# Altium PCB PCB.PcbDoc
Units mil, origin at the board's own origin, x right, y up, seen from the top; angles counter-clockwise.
Board outline 2000 x 1700 mil, 2 copper layers (Top Layer, Bottom Layer), stack 62 mil thick; 59 components, 36 nets, 136 pads, 43 vias.
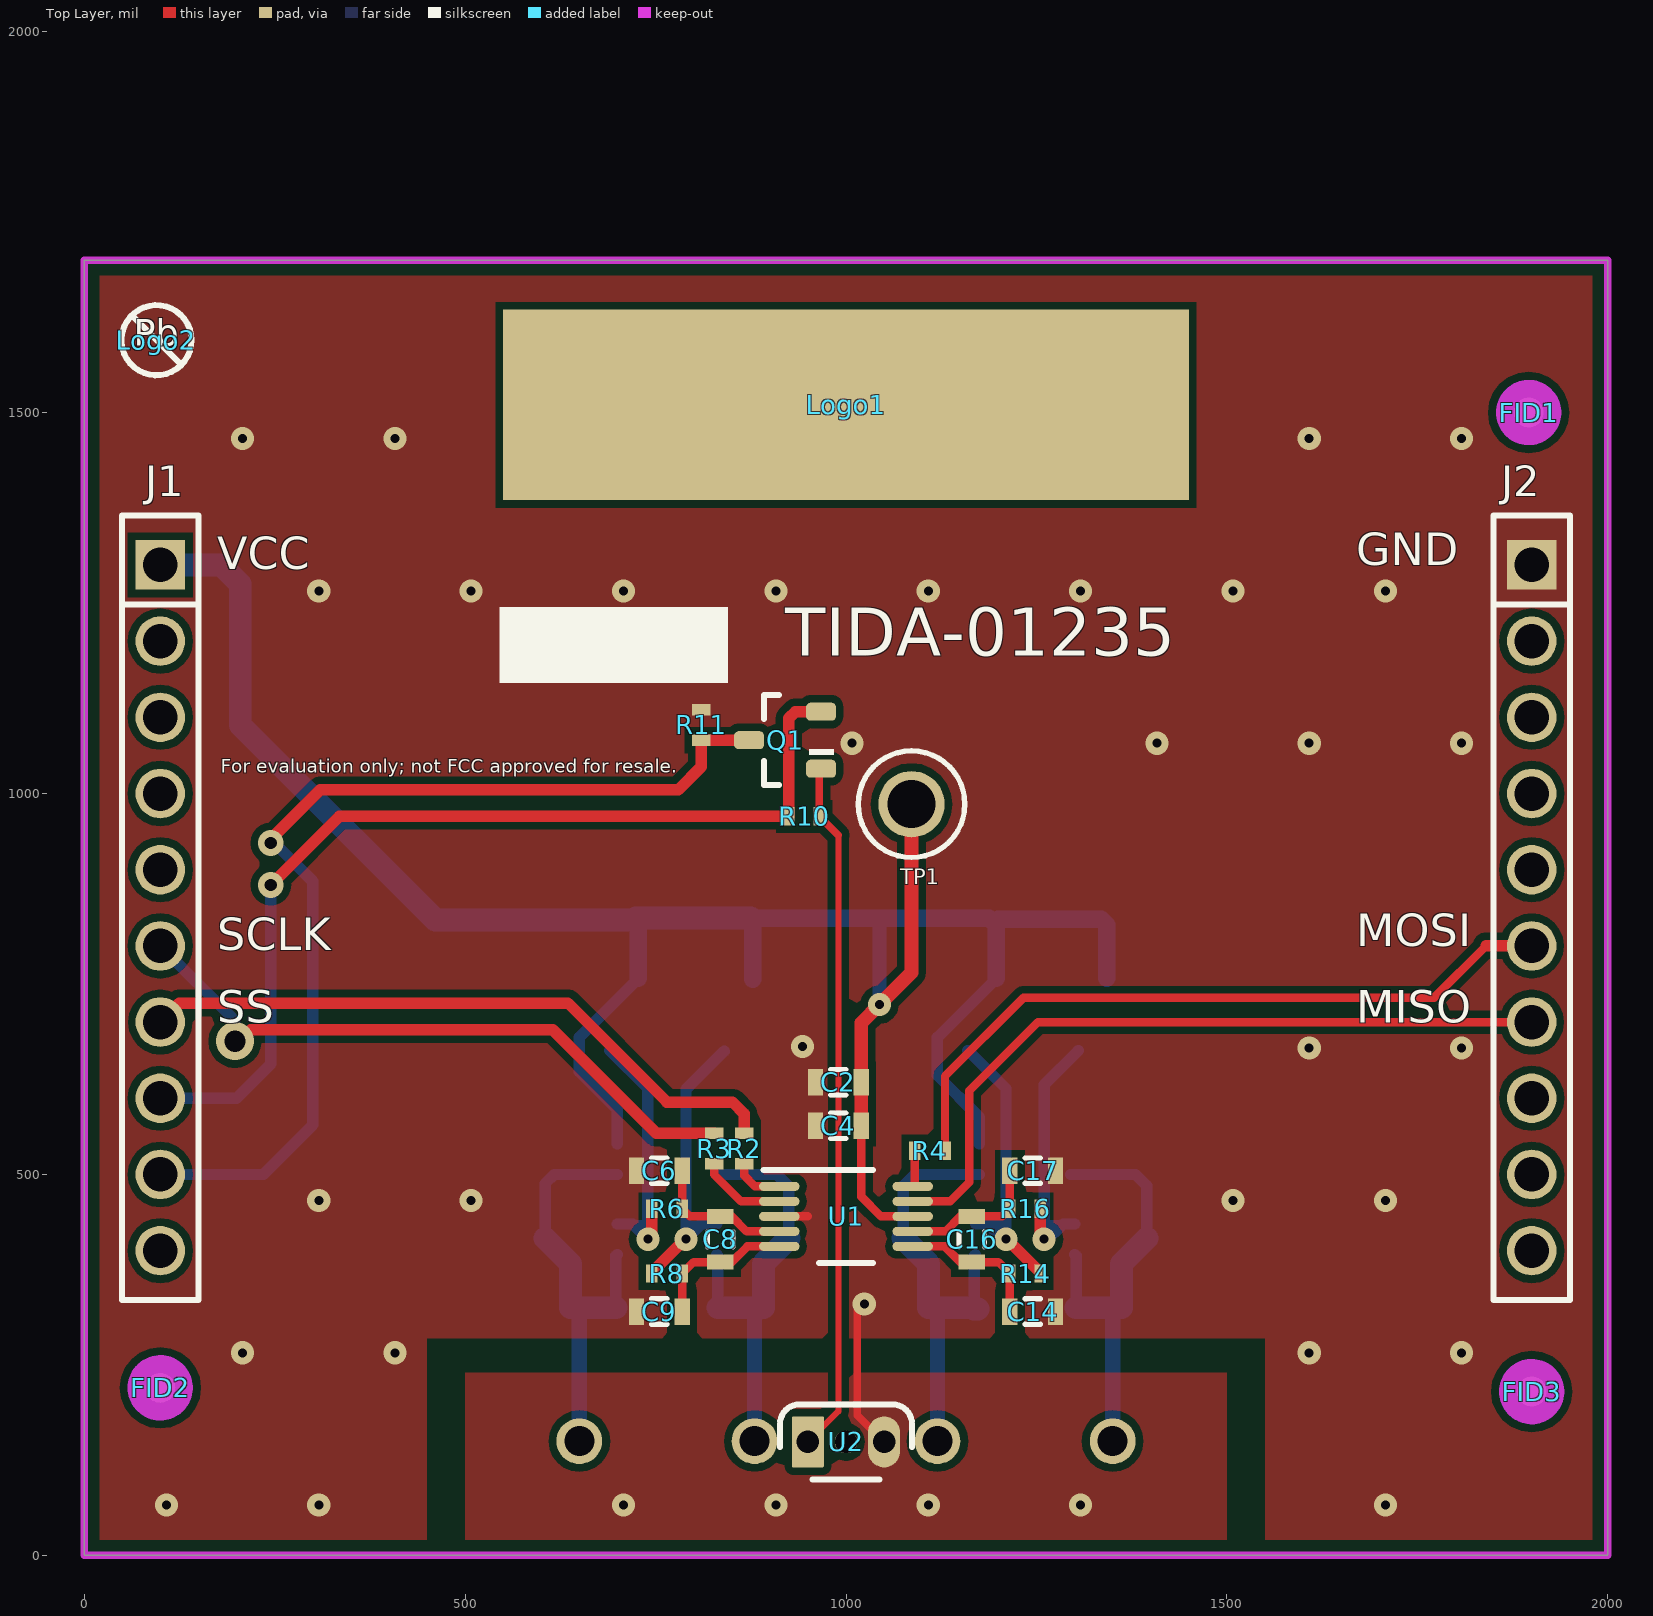
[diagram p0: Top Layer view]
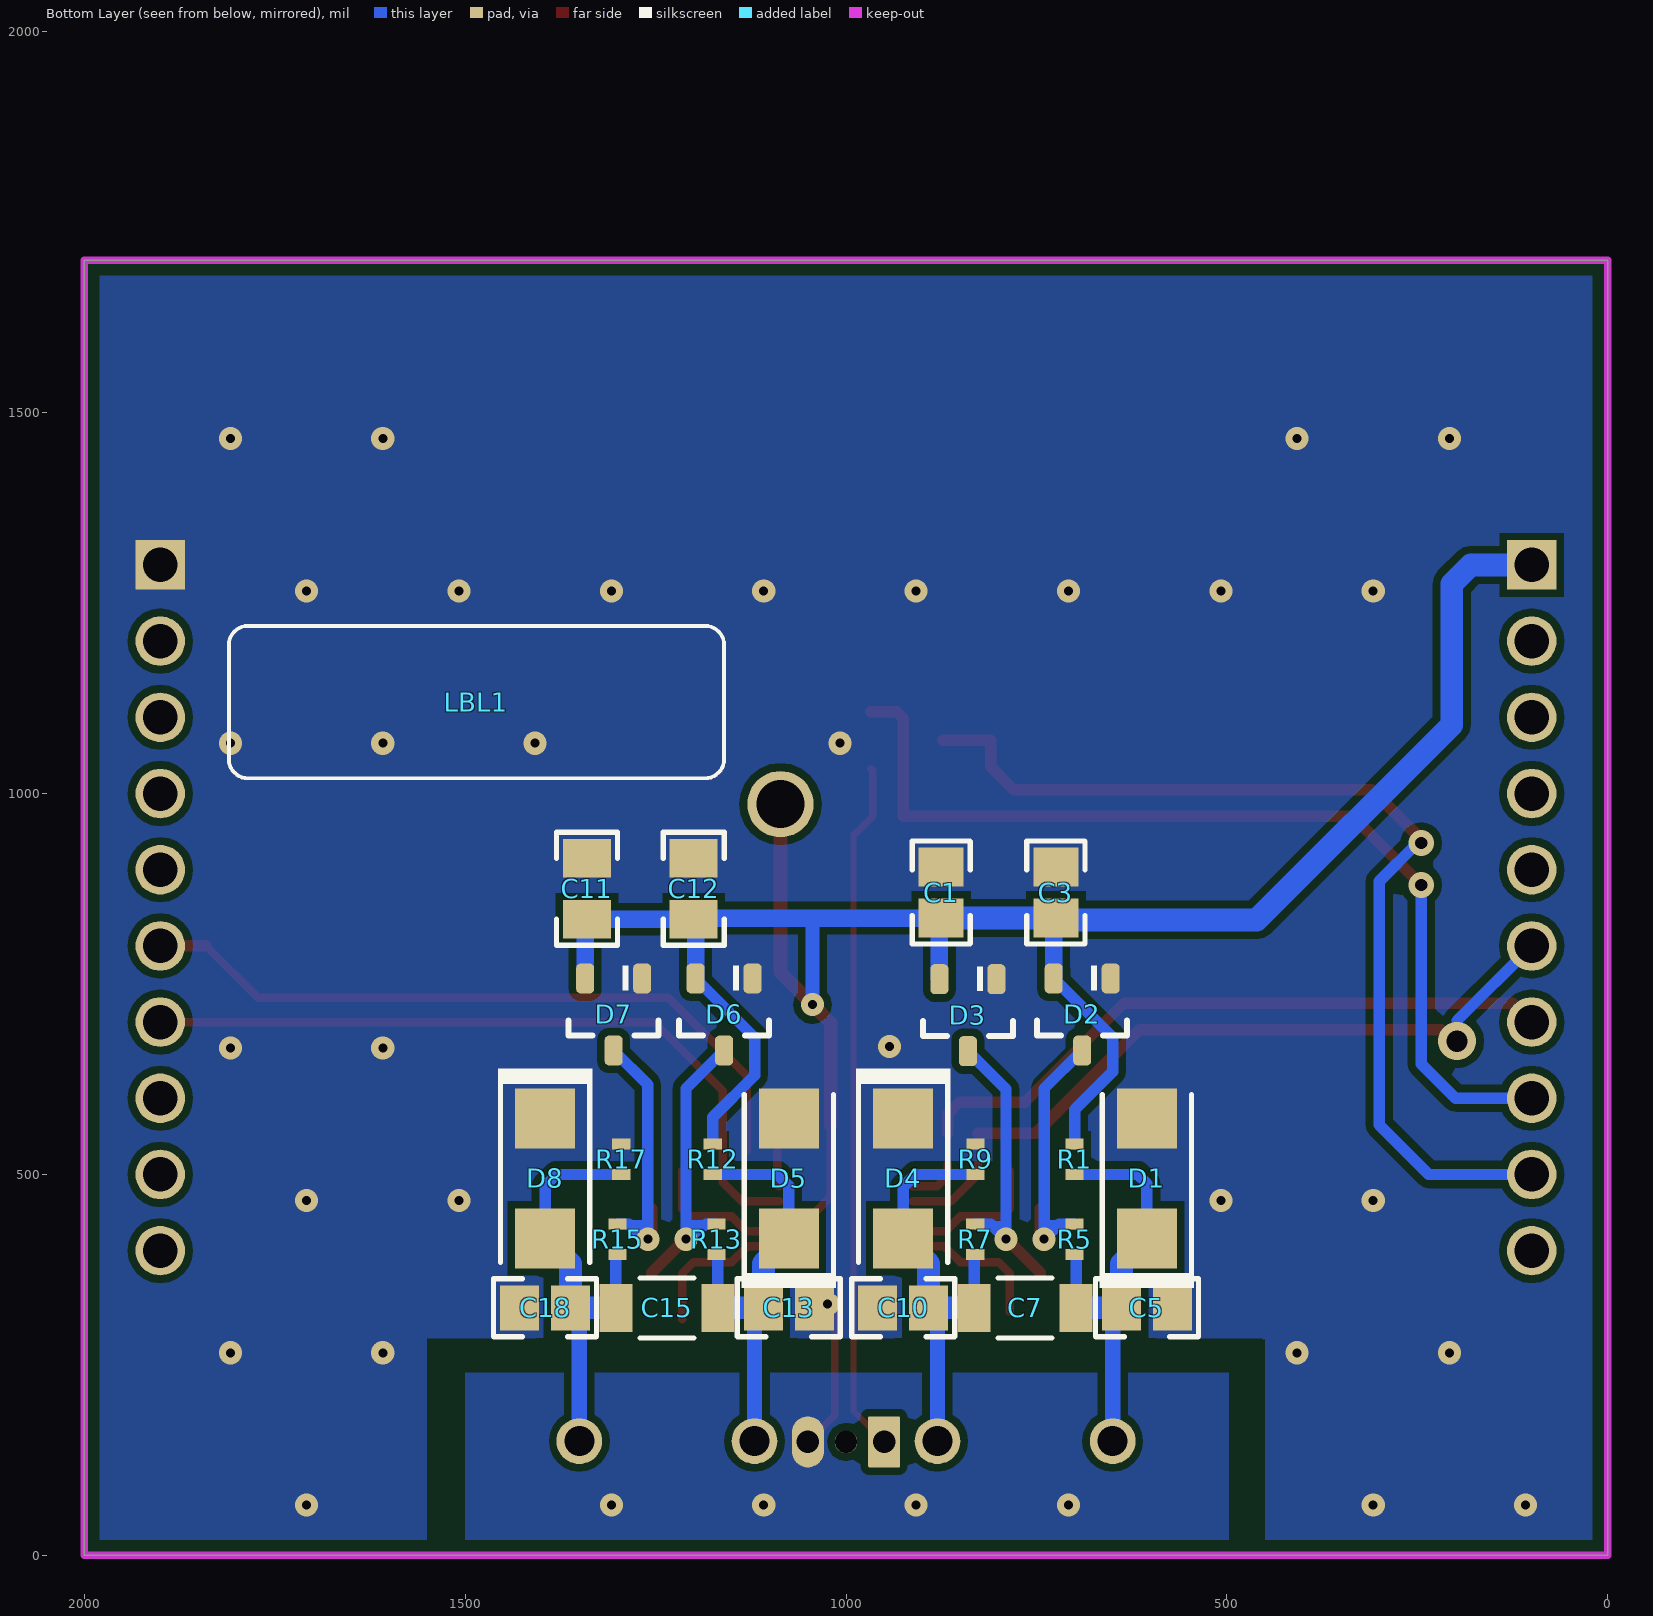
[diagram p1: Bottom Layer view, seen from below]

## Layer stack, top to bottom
Top Solder: solder mask 0.4, Solder Resist, Dk 3.5
Top Layer: signal copper 1.4
Dielectric1: core 59.2, FR-4, Dk 4.8
Bottom Layer: signal copper 1.4
Bottom Solder: solder mask 0.4, Solder Resist, Dk 3.5

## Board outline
0,0 2000,0 2000,1700 0,1700

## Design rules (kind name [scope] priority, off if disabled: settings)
AcuteAngle [All] p1: minimum=4.50000000000000E+0001 checktracksonly=FALSE
AssemblyTestPointUsage [All] p1: valid=2
BoardOutlineClearance BoardOutlineClearance_MountingHoles [OnCopper and InComponentClass('Mounting Holes')] p1: gap=10
BoardOutlineClearance BoardOutlineClearance_Poly [OnCopper and InPoly] p2: gap=10
BoardOutlineClearance [OnCopper and Not InComponentClass('Logo') and not InComponentClass('FiducialMark') and not InRegion(1000,500,4000,800)] p3: gap=20
Clearance Clearance_Keepouts [((IsTrack Or IsArc) And Not InPoly) And IsFree and IsKeepOut vs ((IsTrack Or IsArc) And Not InPoly) And IsFree and IsKeepOut] p1: gap=0
Clearance Clearance_Poly [InPolygon] p2: gap=10
Clearance [All] p3: gap=7.87
ComponentClearance ComponentClearance_MountingHoles_FiducialMarks [InComponentClass('Mounting Holes') vs InComponentClass('FiducialMark')] p1: gap=50 collisioncheckmode=3 verticalgap=10 showdistances=FALSE
ComponentClearance ComponentClearance_Shunt [InComponentClass('Header') vs InComponentClass('Shunt')] p2: gap=0 collisioncheckmode=3 verticalgap=0 showdistances=FALSE
ComponentClearance ComponentClearance_Logo [InComponentClass('Logo')] p3: gap=50 collisioncheckmode=3 verticalgap=10 showdistances=FALSE
ComponentClearance ComponentClearance_ScrewToNut [(HasFootprint('NY PMS 440 0025 PH')) vs (HasFootprint('Keystone_1902C'))] p4: gap=5 collisioncheckmode=3 verticalgap=10 showdistances=FALSE
ComponentClearance ComponentClearance_MountingHoles [InComponentClass('Mounting Holes')] p5: gap=250 collisioncheckmode=3 verticalgap=100000 showdistances=FALSE
ComponentClearance ComponentClearance_SmallPassives [HasFootprint('0201*') or HasFootprint('0402*') or HasFootprint('0508') or HasFootprint('0603*') or HasFootprint('0612') or HasFootprint('0805*') or HasFootprint('0815*') or HasFootprint('0830*') or HasFootprint('1206*') or HasFootprint('1210*') or HasFootprint('1808*') or HasFootprint('1812*') or HasFootprint('1825*') or HasFootprint('2010*') or HasFootprint('2220*') or HasFootprint('2225*') or HasFootprint('2512*') or HasFootprint('2728*') or HasFootprint('3518*') vs HasFootprint('0201*') or HasFootprint('0402*') or HasFootprint('0508') or HasFootprint('0603*') or HasFootprint('0612') or HasFootprint('0805*') or HasFootprint('0815*') or HasFootprint('0830*') or HasFootprint('1206*') or HasFootprint('1210*') or HasFootprint('1808*') or HasFootprint('1812*') or HasFootprint('1825*') or HasFootprint('2010*') or HasFootprint('2220*') or HasFootprint('2225*') or HasFootprint('2512*') or HasFootprint('2728*') or HasFootprint('3518*')] p6: gap=14.96 collisioncheckmode=3 verticalgap=10 showdistances=FALSE
ComponentClearance ComponentClearance_THtoSMT [IsThruComponent vs IsSMTComponent] p7: gap=40 collisioncheckmode=3 verticalgap=30 showdistances=FALSE
ComponentClearance ComponentClearance_THtoTH [IsThruComponent vs IsThruComponent] p8: gap=30 collisioncheckmode=3 verticalgap=30 showdistances=FALSE
ComponentClearance [All] p9: gap=30 collisioncheckmode=3 verticalgap=10 showdistances=FALSE
DiffPairsRouting [All] p1: maxlimit=100 minlimit=10 mostfreqgap=10 toplayer_minwidth=15 toplayer_maxwidth=15 toplayer_prefwidth=15 bottomlayer_minwidth=15 bottomlayer_maxwidth=15 bottomlayer_prefwidth=15 maxuncoupledlength=1000
FabricationTestPointUsage TestPointUsage [All] p1: valid=2 allowmultiple=FALSE
FabricationTestpoint Testpoint [All] p1: side=3 testpointundercomponent=TRUE minsize=40 maxsize=100 preferedsize=60 minholesize=0 maxholesize=40 preferedholesize=32 testpointgrid=1 allowsidetop=TRUE allowsidebottom=TRUE usegrid=TRUE gridtolerance=0.01
FanoutControl Fanout_LCC [IsLCC] p1: bgadir=Out bgaviamode=Centered fanoutstyle=Auto fanoutdirection=Alternating viagrid=1 // Fanout_LCC (Default Rule)
FanoutControl Fanout_BGA [IsBGA] p2: bgadir=Out bgaviamode=Centered fanoutstyle=Auto fanoutdirection=Alternating viagrid=1 // Fanout_BGA (Default Rule)
FanoutControl Fanout_Default [All] p4: bgadir=Out bgaviamode=Centered fanoutstyle=Auto fanoutdirection=Alternating viagrid=1 // Fanout_Default (Default Rule)
FanoutControl Fanout_Small [(CompPinCount < 5)] p5: bgadir=Out bgaviamode=Centered fanoutstyle=Auto fanoutdirection=OutThenIn viagrid=1 // Fanout_Small (Default Rule)
HoleSize [All] p1: absolutevalues=TRUE maxlimit=251 minlimit=7.87 maxpercent=80.000 minpercent=20.000
MinimumAnnularRing MinimumAnnularRing_ThermalPadVias [IsVia and InAnyComponent] p1: minimumring=0
MinimumAnnularRing [All] p2: minimumring=0
MinimumSolderMaskSliver MinimumSolderMaskSliver_Logo [InComponentClass('Logo') vs InComponentClass('Logo')] p1: minsoldermaskwidth=0.7
MinimumSolderMaskSliver [All] p2: minsoldermaskwidth=0
PlaneConnect [All] p1: planeconnectstyle=Relief reliefexpansion=10 reliefentries=4 reliefconductorwidth=10 reliefairgap=10
PolygonConnect [All] p1: connectstyle=Direct reliefconductorwidth=10 reliefentries=4 polygonreliefangle="90 Angle" airgapwidth=10
RoutingVias ThermalPadVias [IsVia and InAnyComponent] p1: holewidth=7.87 width=19.68 viastyle="Through Hole" minholewidth=7.87 minwidth=19.68 maxholewidth=12.99 maxwidth=23.62
RoutingVias [All] p2: holewidth=16 width=34 viastyle="Through Hole" minholewidth=7.87 minwidth=26 maxholewidth=40 maxwidth=65
SilkToBoardRegionClearance [Not ((IsComment or IsDesignator) And (Hide <> 'False')) and not InRegion(1000,500,4000,800)] p1:
SilkToSilkClearance SilkToSilkClearance_Pb-FreeLogo [(HasFootprint('Pb-Free_Overlay_Medium') OR HasFootprint('Pb-Free_Overlay_Small')) vs (HasFootprint('Pb-Free_Overlay_Medium') OR HasFootprint('Pb-Free_Overlay_Small'))] p1: silktosilkclearance=0
SilkToSilkClearance [All] p2: silktosilkclearance=4
SilkToSolderMaskClearance SilkToComponentPadClearance [IsPad and InAnycomponent] p1: minsilkscreentomaskgap=0 clearancetoexposedcopper=TRUE
SilkToSolderMaskClearance "Silk to Solder Mask Opening" [All] p2: minsilkscreentomaskgap=0 clearancetoexposedcopper=FALSE
SolderMaskExpansion [All] p1: expansion=1.97
Width [All] p1: maxlimit=100 minlimit=6 preferedwidth=10 checkconnectedcopper=TRUE
15 further rules are at their usual default settings.

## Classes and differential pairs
component class Logo: Logo1
component class EVM_Hardware: FCC FID1 FID2 FID3 LBL1 Logo1 Logo2 ZZ1 ZZ2 ZZ3 ZZ4
component class FiducialMark: FID1 FID2 FID3
component class AssemblyNote: ZZ1 ZZ2 ZZ3 ZZ4
component class Label: LBL1
component class BlankSheet: C1 C2 C3 C4 C5 C6 C7 C8 C9 C10 C11 C12 C13 C14 C15 C16 C17 C18 D1 D2 D3 D4 D5 D6 D7 D8 J1 J2 J3 Q1 R1 R2 R3 R4 R5 R6 R7 R8 R9 R10 R11 R12 R13 R14 R15 R16 R17 TP1 U1 U2

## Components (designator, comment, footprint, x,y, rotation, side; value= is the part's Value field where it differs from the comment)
C1 "CGA4J2X8R1H104M125AA" 0805 875,870 r270 bottom
C2 "CGA3E3X8R1E224K080AB" 0603S 989.98,621 r180 top
C3 "CGA4J2X8R1H104M125AA" 0805 724.47,870 r270 bottom
C4 "CGA3E3X8R1E224K080AB" 0603S 990,564 r180 top
C5 "CGA4J2X8R1H104M125AA" 0805 605,325 r0 bottom
C6 "C1608NP01H103J080AA" 0603S 755,505 r0 top
C7 "CGA5L3X8R1H105K160AB" 1206_180 765,325 r0 bottom
C8 "C0603C475K8PACTU" 0603S 835,415 r270 top
C9 "C1608NP01H103J080AA" 0603S 755,320 r180 top
C10 "CGA4J2X8R1H104M125AA" 0805 925,325 r0 bottom
C11 "CGA4J2X8R1H104M125AA" 0805_HV 1340,875 r270 bottom
C12 "CGA4J2X8R1H104M125AA" 0805_HV 1200,875 r270 bottom
C13 "CGA4J2X8R1H104M125AA" 0805 1075,325 r0 bottom
C14 "C1608NP01H103J080AA" 0603S 1245,320 r180 top
C15 "CGA5L3X8R1H105K160AB" 1206_180 1235,325 r0 bottom
C16 "C0603C475K8PACTU" 0603S 1165,415 r90 top
C17 "C1608NP01H103J080AA" 0603S 1245,505 r0 top
C18 "CGA4J2X8R1H104M125AA" 0805 1395,325 r0 bottom
D1 "SM4T7V6CAY" SMA 605,495 r90 bottom
D2 "BAV199-TP" SOT-23 690,710 r270 bottom
D3 "BAV199-TP" SOT-23 840,709.06 r270 bottom
D4 "SM4T7V6CAY" SMA 925,495 r270 bottom
D5 "SM4T7V6CAY" SMA 1075,495 r90 bottom
D6 "BAV199-TP" SOT-23 1160,710 r270 bottom
D7 "BAV199-TP" SOT-23 1305,710 r270 bottom
D8 "SM4T7V6CAY" SMA 1395,495 r270 bottom
FID1 "Fiducial" Fiducial10-20 1896,1500 r0 top
FID2 "Fiducial" Fiducial10-20 100,220 r0 top
FID3 "Fiducial" Fiducial10-20 1900,215 r0 top
J1 "SSW-110-23-F-S" CONN_SSW-110-23-F-S 100,850 r90 top
J2 "SSW-110-23-F-S" CONN_SSW-110-23-F-S 1900,850 r90 top
LBL1 "Size: 0.65\" x 0.20 \"" Label_650x200 1485,1120 r0 bottom
Logo1 "Texas Instruments" TI_Stacked_SolderMask_Small 1000,1510 r0 top
Logo2 "Pb-Free Symbol" Pb-Free_Overlay_Small 95,1595 r0 top
Q1 "BC856A-7-F" SOT-23 920,1070 r180 top
R1 "ERJ-U02F2004X" 0402S 700,520 r90 bottom
R2 "ERJ-2GEJ470X" 0402S 866.5,534 r90 top
R3 "ERJ-2GEJ470X" 0402S 827,534 r90 top
R4 "ERJ-2GEJ470X" 0402S 1110,531 r0 top
R5 "ERA-2AEB4990X" 0402S 700,415 r90 bottom
R6 "ERA-2AEB4990X" 0402S 765,455 r0 top
R7 "ERA-2AEB4990X" 0402S 830.32,415 r90 bottom
R8 "ERA-2AEB4990X" 0402S 765,370 r0 top
R9 "ERJ-U02F2004X" 0402S 830,520 r270 bottom
R10 "ERA-2AEB752X" 0402S 945,970 r180 top
R11 "ERJ-2GEJ104X" 0402S 810,1090 r270 top
R12 "ERJ-U02F2004X" 0402S 1175,520 r90 bottom
R13 "ERA-2AEB4990X" 0402S 1170,415 r90 bottom
R14 "ERA-2AEB4990X" 0402S 1235,370 r180 top
R15 "ERA-2AEB4990X" 0402S 1300,415 r90 bottom
R16 "ERA-2AEB4990X" 0402S 1235,455 r180 top
R17 "ERJ-U02F2004X" 0402S 1295,520 r270 bottom
TP1 "5126" Keystone5126 1086,986 r0 top
U1 "ADS1118QDGSRQ1" DGS0010A_N 1000,445 r0 top
U2 "LMT01QLPGMQ1" LPG0002A 1000,149 r0 top
ZZ1 "This Assembly Note is for PCB labels only" AssemblyNoteLabel 185,3938 r0 top
ZZ2 "These assemblies are ESD sensitive, ESD precautions shall be observed." AssemblyNote 185,3829.11 r0 top
ZZ3 "These assemblies must be clean and free from flux and all contaminants. Use of no clean flux is not acceptable." AssemblyNote 185,3740.56 r0 top
ZZ4 "These assemblies must comply with workmanship standards IPC-A-610 Class 2, unless otherwise specified." AssemblyNote 185,3652 r0 top

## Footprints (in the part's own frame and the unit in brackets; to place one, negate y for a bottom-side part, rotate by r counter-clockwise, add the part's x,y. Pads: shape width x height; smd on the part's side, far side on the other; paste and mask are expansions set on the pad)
0402S [mil] "Based on C0402S footprint from PADS legacy"
  rect 15x24 smd: 1(-20,0) 2(20,0)
  body extent -22,-12 22,12, height 24
0603S [mil]
  rect 20x35 smd: 1(-30,0) 2(30,0)
  silkscreen extent -10,-17 10,17, body extent -34,-19 34,19, height 39
0805 [mm] "0805 from SM-752 data"
  rect 1.3x1.5 smd: 1(-0.85,0) 2(0.85,0)
  silkscreen extent -1.72,-0.97 1.72,0.97, body extent -1.1,-0.72 1.1,0.72, height 1.45
0805_HV [mil] "0805 with 30mil clearance between pads"
  rect 50x63 smd: 1(-40,0) 2(40,0)
  silkscreen extent -74,-40 74,40, body extent -43,-29 43,29, height 57
1206_180 [mm] "1206_180"
  rect 1.1x1.6 smd: 1(-1.7,0) 2(1.7,0)
  silkscreen extent -0.9,-1 0.9,1, body extent -1.75,-0.95 1.75,0.95, height 1.8
AssemblyNote [mil] "Assembly Note"
AssemblyNoteLabel [mil] "Assembly Note for PCB Labels"
CONN_SSW-110-23-F-S [mm] "SAMTEC"
  rect 1.65x1.65 hole 1.15: 1(11.43,0)
  round 1.65 hole 1.15: 2(8.89,0) 3(6.35,0) 4(3.81,0) 5(1.27,0) 6(-1.27,0) 7(-3.81,0) 8(-6.35,0) 9(-8.89,0) 10(-11.43,0)
  silkscreen extent -13.08,-1.27 13.08,1.27, body extent -13,-1.27 13,1.27, height 8.59
DGS0010A_N [mm] "TSSOP, 10-Leads, Body 3x3mm, Pitch 0.5mm, IPC Medium Density"
  oval 1.35x0.3 smd: 1(-2.225,1) 2(-2.225,0.5) 3(-2.225,0) 4(-2.225,-0.5) 5(-2.225,-1) 6(2.225,-1) 7(2.225,-0.5) 8(2.225,0) 9(2.225,0.5) 10(2.225,1)
  silkscreen extent -2.75,-1.55 0.9,1.55, body extent -2.45,-1.5 2.45,1.5, height 0.96
Fiducial10-20 [mm]
  round 1 smd mask+0.5: 1(0,0)
  Top Layer keep-out circle w1.178: c0,0 r0.5
Keystone5126 [mil] "Keystone Multipurpose loops"
  round 87 hole 63: 1(0,0)
  silkscreen extent -70,-70 70,70, body extent -63,-63 63,62, height 319
Label_650x200 [mil] "Thermal Transfer Label"
  round 1 on Mech14: 0(0,0)
  silkscreen extent -325,-100 325,100, body extent -325,-100 325,100, height 1
LPG0002A [mm] "TO, 2-Leads, Body 4x1.52mm"
  rrect9% 1.07x1.7 hole 0.75: 1(-1.27,0)
  rrect100% 1.07x1.7 hole 0.75: 2(1.27,0)
  round 0.75 hole 0.75 unplated paste+0 mask+0: MH(0,0)
  silkscreen extent -2.21,-1.25 2.21,1.25, body extent -2,-0.98 2,0.54, height 5.06
Pb-Free_Overlay_Small [mil]
  silkscreen extent -46,-46 46,46
SMA [mm] "Molded Diode, 2-Leads, Body 4.3x2.6mm, IPC Medium Density, based on OnSemi component dimensions and land pattern"
  rect 2x2 smd: 1(-2,0) 2(2,0)
  silkscreen extent -3.66,-1.57 2.79,1.57, body extent -2.6,-1.3 2.6,1.3, height 2.42
SOT-23 [mm] "SOT23, 3-Leads, Body 2.9x1.3mm, Pitch 0.95mm, Lead Span 2.5mm, IPC Medium Density"
  rrect50% 1x0.6 smd: 1(-1.2,0.95) 2(-1.2,-0.95) 3(1.2,0)
  silkscreen extent -1.62,-1.5 0.7,1.5, body extent -1.16,-1.45 1.21,1.45, height 1
TI_Stacked_SolderMask_Small [mil]
  rect 900x250 smd paste-125 mask-125: 0(0,0)

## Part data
C1 C3 C5 C10 C11 C12 C13 C18: "CAP, CERM, 0.1 µF, 50 V, +/- 20%, X8R, AEC-Q200 Grade 0, 0805"
C2 C4: "CAP, CERM, 0.22 µF, 25 V, +/- 10%, X8R, AEC-Q200 Grade 0, 0603"
C6 C9 C14 C17: "CAP, CERM, 0.01 µF, 50 V, +/- 5%, C0G/NP0, 0603"
C7 C15: "CAP, CERM, 1 µF, 50 V, +/- 10%, X8R, AEC-Q200 Grade 0, 1206"
C8 C16: "CAP, CERM, 4.7 µF, 10 V, +/- 10%, X5R, 0603"
D1 D4 D5 D8: "Diode, TVS, Bi, 6.5 V, 400 W, AEC-Q101, SMA"
D2 D3 D6 D7: "Diode, Switching, 70 V, 0.215 A, SOT-23"
FID1 FID2 FID3: "Fiducial mark.  There is nothing to buy or mount."
J1 J2: "Connector, Receptacle, 100mil, 10x1, Gold plated, TH"
LBL1: library part THT-14-423-10, "Thermal Transfer Printable Labels, 0.650\" W x 0.200\" H - 10,000 per roll"
Logo1: library part TI_Logo, "Texas Instrument Corporate Signature"
Logo2: library part Pb-Free
Q1: library part "BC856A-7-F, Diodes Inc.", "Transistor, PNP, 65 V, 0.01 A, SOT-23"
R1 R9 R12 R17: "RES, 2.00 M, 1%, 0.1 W, AEC-Q200 Grade 0, 0402"
R2 R3 R4: "RES, 47, 5%, 0.1 W, AEC-Q200 Grade 0, 0402"
R5 R6 R7 R8 R13 R14 R15 R16: "RES, 499, 0.1%, 0.063 W, AEC-Q200 Grade 0, 0402"
R10: "RES, 7.50 k, 0.1%, 0.063 W, AEC-Q200 Grade 0, 0402"
R11: "RES, 100 k, 5%, 0.1 W, AEC-Q200 Grade 0, 0402"
TP1: "Test Point, Multipurpose, Green, TH"
U1: "Low-Power, SPI-Compatible, 16-Bit Analog-to-Digital Converter With Internal Reference and Temperature Sensor, DGS0010A"
U2: "0.5°C Accurate 2-Pin Digital Output Temperature Sensor with Pulse Count Interface, LPG0002A (TO-92-2)"
ZZ1: library part AssemblyNoteLabel
ZZ2 ZZ3 ZZ4: library part AssemblyNote

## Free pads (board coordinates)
  round 60 hole 39.37: 0(1350,150) ""(650,150) ""(880,150) ""(1120,150)

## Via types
v1: diameter 30.32, hole 11.81, Top Layer to Bottom Layer, 40 vias
v2: diameter 34, hole 16, Top Layer to Bottom Layer, 2 vias
v3: diameter 50, hole 28, Top Layer to Bottom Layer, 1 vias

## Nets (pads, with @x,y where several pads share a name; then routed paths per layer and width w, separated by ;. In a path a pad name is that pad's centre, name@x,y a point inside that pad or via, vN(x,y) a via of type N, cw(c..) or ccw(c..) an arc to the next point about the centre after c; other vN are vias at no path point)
AN0: C6.2 C8.1 R6.2 U1.4 | length 189.7
  Top Layer w11: C6.2 R6.2 795,445 850,445 869.68,425.32 U1.4
AN1: C8.2 C9.1 R8.2 U1.5 | length 192.2
  Top Layer w11: C9.1 R8.2 800,385 850,385 870.63,405.63 U1.5
AN2: C14.2 C16.1 R14.2 U1.6 | length 202.2
  Top Layer w11: U1.6 1129.37,405.63 1150,385 1200,385 R14.2 C14.2@1215,310
AN3: C16.2 C17.1 R16.2 U1.7 | length 189.7
  Top Layer w11: U1.7 1130.32,425.32 1150,445 1205,445 R16.2 C17.1
GND: C1.1 C2.2 C3.1 C4.2 C5.1 C6.1 C9.2 C10.2 C11.1 C12.1 C13.1 C14.1 C17.2 C18.2 D1.2 D2.1 D3.1 D4.1 D5.2 D6.1 D7.1 D8.1 J2.1 R9.1 R11.1 R17.1 U1.3 U2.2 | length 230.1
  Top Layer w10: v1@1015,327 1015,184 U2.2
  Top Layer w11: U1.3 950,445
  other v1: 108,66 308,66 708,66 908,66 1108,66 1308,66 1708,66 208,266 408,266 1608,266 1808,266 1024,330 308,466 508,466 1508,466 1708,466 1608,666 1808,666 943,668 1008,1066 1408,1066 1608,1066 1808,1066 308,1266 508,1266 708,1266 908,1266 1108,1266 1308,1266 1508,1266 1708,1266 208,1466 408,1466 1608,1466 1808,1466
J1.2: J1.2
J1.3: J1.3
J1.4: J1.4
J1.5: J1.5
J1.6: J1.6 R3.2 | length 829.9
  Top Layer w15: 219,690 615,690 751,554 R3.2
  Bottom Layer w15: J1.6 198,702 v3(198,675)
J1.7: J1.7 R2.2 | length 876.8
  Top Layer w15: J1.7@110,690 J1.7 125,725 635,725 765,595 851,595 866.5,579.5 R2.2
J1.8: J1.8 Q1.2 R10.2 | length 1290.6
  Top Layer w15: v2(245,880) 335,970 R10.2 925,1098.84 933.56,1107.4 Q1.2
  Bottom Layer w15: J1.8 200,600 245,645 v2(245,880)
J1.9: J1.9 Q1.3 R11.2 | length 1324.7
  Top Layer w15: v2@245,940 310,1005 780,1005 810,1035 R11.2 Q1.3
  Bottom Layer w15: J1.9 235,500 300,565 300,885 250,935 v2(245,935)
J1.10: J1.10
J2.2: J2.2
J2.3: J2.3
J2.4: J2.4
J2.5: J2.5
J2.6: J2.6 R4.2 | length 938.8
  Top Layer w11: R4.2 1130,629 1233,732 1772,732 1840,800
  Top Layer w15: 1840,800 J2.6
J2.7: J2.7 U1.9 | length 980.2
  Top Layer w11: U1.9 1136.69,464.69 1162,490 1162,610 1252,700 J2.7
J2.8: J2.8
J2.9: J2.9
J2.10: J2.10
NetD2_3: D2.3 R5.2 R6.1 | length 363.8
  Top Layer w15: v1@740,420 v1(740,415) 745,420 R6.1
  Bottom Layer w15: D2.3 740,612.76 v1(740,415) 720,435 R5.2
NetD3_3: D3.3 R7.2 R8.1 | length 379.2
  Top Layer w15: R8.1 745,371.24 v1@788.76,415
  Bottom Layer w15: R7.2 810,435 v1(790,415) 790,611.81 D3.3
NetD6_3: D6.3 R13.2 R14.1 | length 375.8
  Top Layer w15: v1(1210,415) 1211.24,415 1255,371.24 R14.1
  Bottom Layer w15: D6.3 1210,612.76 v1(1210,415) 1183.78,435 ; R13.2 R13.2@1180,435
NetD7_3: D7.3 R15.2 R16.1 | length 363.8
  Top Layer w15: R16.1 1255,420 v1(1260,415)
  Bottom Layer w15: R15.2 1285,435 1260,410 v1(1260,415) 1260,617.76 D7.3
NetQ1_1: Q1.1 R10.1 U2.1 | length 911.4
  Top Layer w8: U2.1 990.06,189.07 989.93,945.07
  Top Layer w10: Q1.1 965,1030.35 R10.1 989.93,945.07
NetR2_1: R2.1 U1.1 | length 67.3
  Top Layer w11: R2.1 866.5,498.5 880.63,484.37 U1.1
NetR3_1: R3.1 U1.2 | length 114
  Top Layer w11: R3.1 827,500 862.31,464.69 U1.2
NetR4_1: R4.1 U1.10 | length 46.6
  Top Layer w11: U1.10 1090,486.77 R4.1@1090,530
TC1+: C5.2 C7.1 D1.1 pad.@650,150 R1.1 R5.1 | length 587
  Bottom Layer w15: D1.1 605,488 617,500 R1.1 ; C7.1 698.07,393.07 R5.1
  Bottom Layer w20: C5.2 650,313.46 pad.@650,150
  Bottom Layer w30: D1.1 638.46,382.8 C5.2 C7.1
TC1-: C7.2 C10.1 D4.2 pad.@880,150 R7.1 R9.2 | length 584.5
  Bottom Layer w15: R9.2 909,500 925,484 D4.2 ; R7.1 831.93,393.39 C7.2
  Bottom Layer w20: pad.@880,150 880,313.46 C10.1
  Bottom Layer w30: C7.2 C10.1 891.54,382.8 D4.2
TC2+: C13.2 C15.1 D5.1 pad.@1120,150 R12.1 R13.1 | length 627
  Bottom Layer w12: 1143.9,500 R12.1
  Bottom Layer w15: D5.1 1075,485 1090,500 R12.1 ; C15.1 1168.07,393.07 R13.1
  Bottom Layer w20: C13.2 1120,313.46 pad.@1120,150
  Bottom Layer w30: D5.1 1108.46,382.8 C13.2 1166.47,325 1168.03,323.44 C15.1@1173.07,323.31
TC2-: C15.2 C18.1 D8.2 pad.0 R15.1 R17.2 | length 590.3
  Bottom Layer w15: R17.2 1380,500 1395,485 D8.2 ; R15.1 1301.93,393.07 C15.2
  Bottom Layer w20: pad.0 1350,313.46 C18.1
  Bottom Layer w30: C15.2 C18.1 1361.54,382.8 D8.2
VCC: C1.2 C2.1 C3.2 C4.1 C11.2 C12.2 D2.2 D3.2 D6.2 D7.2 J1.1 R1.2 R12.2 TP1.1 U1.8 | length 3125.3
  Top Layer w11: C4.1 1020,471 1046,445 U1.8
  Top Layer w18: C4.1 C2.1 1019.98,698.98 v1(1044,723) 1086,765 TP1.1
  Bottom Layer w15: R1.2 700,585 650,635 650,679.84 D2.2 ; R12.2 1175,575 1120,630 1120,679.84 D6.2
  Bottom Layer w18: 1043,836.54 1044,835.54 v1(1044,723)
  Bottom Layer w23: C3.2 C3.2@726.87,834.13 ; D2.2 C3.2@727.4,833.6 ; C1.2 1043,836.54 1188.27,836.54 1197.4,827.4 D6.2 ; D3.2 C1.2@877.4,834.13 ; C12.2 1335,835 1342.4,827.6 D7.2
  Bottom Layer w30: J1.1 180,1300 205,1275 205,1090 460.87,834.13 C3.2@726.87,834.13 ; C3.2 C1.2
pads on no net: FID1.1 FID2.1 FID3.1 LBL1.0 Logo1.0 U2.MH

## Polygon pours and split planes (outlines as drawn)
GND on Bottom Layer "BOTTOM_LAYER_GND_P004" (solid, remove dead copper, pour order 4): 5,0 5,1700 1995,1700 1995,0
GND on Top Layer "TOP_LAYER_GND_P008" (solid, remove dead copper, pour order 8): 5,0 5,1700 1995,1700 1995,0

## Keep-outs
Keep-Out Layer:
  the board outline again, w10
  text ".Layer_Name" at 577,-858.49 h60

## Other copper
Top Layer:
  pour cut-out: 500,75 500,240 500,255 475,255 450,255 450,240 450,0 500,0 500,30
  pour cut-out: 1500,0 1500,240 1505,245 1550,245 1550,0
  pour cut-out: 450,285 1550,285 1550,235 1545,240 450,240
  text ".Layer_Name" at 577,-858.49 h60
Bottom Layer:
  rectangle net NetD2_3: 713.78,430 735,440
  rectangle net NetD3_3: 789.09,428.78 810.32,438.78
  rectangle net NetD6_3: 1188.78,428.78 1210,440
  rectangle net NetD7_3: 1260,425 1281.22,440
  pour cut-out: 500,0 450,0 450,285 451.72,283.28 497.82,283.28 497.82,2.18
  pour cut-out: 1550,0 1550,285 1503.16,285 1500,281.84 1500,0
  pour cut-out: 451.72,283.28 453.45,285 1550,285 1550,240 450,240
  text ".Layer_Name" at 577,-858.49 h60

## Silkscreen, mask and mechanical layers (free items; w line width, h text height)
Top Overlay:
  region: 845,1245 545,1245 545,1145 845,1145
  text "GND" at 1670,1285 h72.83
  text "VCC" at 175,1280 h72.83
  text "TIDA-01235" at 920,1160 h108.27
  text "For evaluation only; not FCC approved for resale." at 179.51,1021.42 h30
  text "MOSI" at 1670,785 h72.83
  text "SCLK" at 175,780 h72.83
  text "SS" at 175,685 h72.83
  text "MISO" at 1670,685 h72.83
  text ".Layer_Name" at 577,-858.49 h60
Bottom Overlay:
  text ".Layer_Name" at 577,-858.49 h60
Top Paste:
  text ".Layer_Name" at 577,-858.49 h60
Bottom Paste:
  text ".Layer_Name" at 577,-858.49 h60
Top Solder:
  text ".Layer_Name" at 577,-858.49 h60
  text ".Layer_Name" at 577,-858.49 h60
Bottom Solder:
  text ".Layer_Name" at 577,-858.49 h60
Drill Guide:
  text ".Layer_Name" at 577,-858.49 h60
M1 Board Outline:
  the board outline again, w10
  text ".Layer_Name" at 577,-858.49 h60
M2 Board Dimensions:
  rectangle: 0,-275 125,-150
  rectangle: 125,-400 500,-275
  lines w7: 0,-275 1000,-275 ; 125,-400 125,-150 ; 250,-400 250,-150 ; 500,-400 500,-150 ; 750,-400 750,-150 ; 0,-400 1000,-400 1000,-150 0,-150 0,-400
  text ".Layer_Name" at 577,-858.49 h60
M3 3D STEP Top:
  text ".Layer_Name" at 577,-858.49 h60
M4 3D STEP Bottom:
  text ".Layer_Name" at 577,-858.49 h60
M5 Assembly Top:
  lines w10: -292,-930.17 6308,-930.17 ; -292,-726.83 6310,-726.83 ; -292,-523.5 -292,-1133.5 3713,-1133.5 6310,-1133.5 6310,-523.5 -291.5,-523.5 -291.5,-1133.5 1284,-1133.5 ; 2173,-1133.5 2173,-523.5 ; 3440,-726.83 3440,-523.5 ; 4280,-726.83 4280,-523.5 ; 4902,-1140 4902,-937.17
  text "COMPONENTS MARKED 'DNP' SHOULD NOT BE POPULATED." at 1153.5,-318.5 h60
  text "ASSEMBLY VARIANT:" at 1153,-434 h60
  text ".VariantName" at 2189,-434 h60
  text "PCB VIEWED FROM TOP SIDE" at -228.5,-655.67 h60
  text "BOARD #:" at 2248,-655.67 h60
  text ".PRJ_Number" at 2793.5,-655.67 h60
  text "REV:" at 3638,-655.67 h60
  text ".PCB_Rev" at 3929.5,-655.67 h60
  text "SVN REV:" at 4476,-655.67 h60
  text ".VersionControl_RevNumber" at 4982,-655.67 h60
  text "TID #:" at 2248,-859 h60
  text ".TID" at 2793.5,-859 h60
  text "PLOT NAME =" at -228.5,-1064.34 h60
  text ".plot_File_Name" at 577,-1064.34 h60
  text "GENERATED    :" at 2250,-1064.34 h60
  text ".Print_Date" at 3119.5,-1064.34 h60
  text ".Print_Time" at 3848.5,-1064.34 h60
  text "TEXAS INSTRUMENTS" at 5113,-1064.34 h60
M6 Assembly Bottom:
  lines w10: -292.5,-727.33 6309.5,-727.33 ; -290.5,-930.67 6309.5,-930.67 ; 1115.5,-1140.5 1115.5,-937.67 ; 1737.5,-727.33 1737.5,-524 ; 2577.5,-727.33 2577.5,-524 ; 3844.5,-1134 3844.5,-524 ; 4733.5,-1134 6309,-1134 6309,-524 -292.5,-524 -292.5,-1134 2304.5,-1134 6309.5,-1134 6309.5,-524
  text "COMPONENTS MARKED 'DNP' SHOULD NOT BE POPULATED." at 6102,-318 h60
  text ".VariantName" at 5058,-434 h60
  text "ASSEMBLY VARIANT:" at 6097,-434 h60
  text ".VersionControl_RevNumber" at 1035.5,-656.17 h60
  text "SVN REV:" at 1541.5,-656.17 h60
  text ".PCB_Rev" at 2088,-656.17 h60
  text "REV:" at 2379.5,-656.17 h60
  text ".PRJ_Number" at 3224,-656.17 h60
  text "BOARD #:" at 3769.5,-656.17 h60
  text "PCB VIEWED FROM BOTTOM SIDE" at 6246,-656.17 h60
  text ".TID" at 3224,-859.5 h60
  text "TID #:" at 3769.5,-859.5 h60
  text "TEXAS INSTRUMENTS" at 904.5,-1064.84 h60
  text ".Print_Time" at 2169,-1064.84 h60
  text ".Print_Date" at 2898,-1064.84 h60
  text "GENERATED    :" at 3767.5,-1064.84 h60
  text ".plot_File_Name" at 5440.5,-1064.84 h60
  text "PLOT NAME =" at 6246,-1064.84 h60
M9 Title Sheet:
  drawing of 57 lines, arcs and shapes, not listed
  text "1" at 739.84,8036.5 h70
  text "2" at 3235.5,8036.5 h70
  text "3" at 5724.84,8036.5 h70
  text "4" at 8231.51,8036.5 h70
  text "5" at 10730.5,8036.5 h70
  text "6" at 13235.5,8036.5 h70
  text "A" at -416.5,6893.5 h70
  text "A" at 14383.5,6893.5 h70
  text "B" at -416.5,4513.5 h70
  text "B" at 14383.5,4513.5 h70
  text "C" at -416.5,2138.5 h70
  text "C" at 14383.5,2138.5 h70
  text "PROJECT TITLE:" at 11343.5,277.5 h45
  text ".PRJ_Title" at 11393.5,144.17 h70
  text "DESIGNED FOR:" at 11343.5,-23.5 h45
  text ".PRJ_Customer" at 11393.5,-163.5 h70
  text "D" at -416.5,-231.5 h70
  text "D" at 14383.5,-231.5 h70
  text "FILE NAME:" at 11343.5,-323.5 h45
  text ".PCB_File_Name_No_Path" at 11393.5,-443.5 h70
  text "Texas Instruments (TI) and/or its licensors do not warrant the accuracy or completeness of this specification" at 6374,-605.34 h45
  text "ENGINEER:" at 11343.5,-613.5 h45
  text "LAYOUT BY:" at 12848.5,-613.5 h45
  text "or any information contained therein. TI and/or its licensors do not warrant that this design will meet" at 6329.01,-718 h45
  text ".PRJ_Engineer" at 11393.5,-768.49 h70
  text ".PCB_Layout" at 12899,-768.49 h70
  text "the specifications, will be suitable for your application or fit for any particular purpose, or will operate in" at 6329.01,-830.67 h45
  text ".Layer_Name" at 577,-858.49 h60
  text "ALTIUM DESIGNER VERSION:" at 12848.5,-923.5 h45
  text "an implementation. TI and/or its licensors do not warrant that the design is production worthy. You should" at 6329.01,-943.33 h45
  text "completely validate and test your design implementation to confirm the system functionality for your application." at 6374,-1056 h45
  text ".print_Scale" at 11393.5,-1056.83 h70
  text ".Application_BuildNumber" at 12899,-1056.83 h70
  text "1" at 739.84,-1263.5 h70
  text "2" at 3235.5,-1263.5 h70
  text "3" at 5724.84,-1263.5 h70
  text "4" at 8231.51,-1263.5 h70
  text "5" at 10730.5,-1263.5 h70
  text "6" at 13235.5,-1263.5 h70
M10 Fab Notes:
  drawing of 173 lines, arcs and shapes, not listed
  text "DESIGN INFORMATION" at 12378.02,6201 h60
  text "MIN. TRACK WIDTH:" at 11733.46,6021 h60
  text "8" at 12829.7,6021 h60
  text "MIL" at 12984.46,6021 h60
  text "MIN. CLEARANCE:" at 11733.46,5889 h60
  text "0.2" at 12769.7,5889 h60
  text "mm" at 12984.46,5889 h60
  text "MIN. VIA PAD SIZE:" at 11733.46,5757 h60
  text "24" at 12799.71,5757 h60
  text "MIL" at 12984.46,5757 h60
  text "0.05mm (2MIL)" at 12428.46,5615.29 h60
  text "MINIMUM ANNULAR RING" at 11404.23,5611 h60
  text "EXTERNAL" at 13136.46,5611 h60
  text "PER" at 11604.23,5493 h60
  text "IPC-D-275 CLASS 2 LEVEL C" at 11824.23,5493 h60
  text "MIL, HOLES" at 13312.46,5380.71 h60
  text "+/-" at 12920,5380 h60
  text "+/-" at 13774,5380 h60
  text "REGISTRATION TOLERANCES:" at 11404.23,5375 h60
  text "METAL" at 12604,5375 h60
  text "5" at 13180.2,5375 h60
  text "3" at 14013.2,5375 h60
  text "MIL" at 14129.46,5375 h60
  text "+/-" at 13774,5262 h60
  text "HOLE SIZE TOLERANCE (UNLESS OTHERWISE SPECIFIED):" at 11404.23,5257 h60
  text "3" at 14013.2,5257 h60
  text "MIL" at 14129.46,5257 h60
  text "MATERIAL:" at 11329.46,5047.54 h60
  text "FR-4 High Tg" at 12315.9,4907.21 h60
  text "FR-408" at 11750.46,4898.64 h60
  text "OTHER" at 13238.46,4898.64 h60
  text "X" at 12161,4895 h60
  text "62 MIL (1.6mm) +/-10%" at 12070.56,4735.92 h60
  text "THICKNESS:" at 11404.23,4731.64 h60
  text "X" at 11942.4,4731.64 h60
  text "OTHER" at 13355.46,4731.64 h60
  text "TOLERANCE:" at 11404.23,4573.64 h60
  text "X" at 12243.53,4573.64 h60
  text "ANSI IPC-6012 TYPE 3 CLASS 2" at 12430.48,4573.64 h60
  text "OTHER +/-" at 12430.46,4417.64 h60
  text "BOW & TWIST:" at 11404.23,4260.64 h60
  text "X" at 12243.53,4260.64 h60
  text "ANSI IPC-6012 TYPE 3 CLASS 2" at 12430.48,4260.64 h60
  text "OTHER +/-" at 12430.46,4102.13 h60
  text "DRILLING:" at 11329.46,3963.64 h60
  text "REFERENCE:" at 11404.23,3846.64 h60
  text "X" at 12052.46,3846.64 h60
  text "AS SHOWN" at 12239.46,3846.64 h60
  text "X" at 12953.46,3846.64 h60
  text "NC_DRILL FILES" at 13090.46,3846.64 h60
  text "PTH COPPER THICKNESS:" at 11404.23,3688.64 h60
  text "X" at 12534.46,3688.64 h60
  text "20-30 um" at 12671.46,3688.64 h60
  text "OTHER" at 13388.46,3688.64 h60
  text "BOARD FINISH:" at 11329.46,3529.64 h60
  text "SILKSCREEN:" at 11484.68,3411.64 h60
  text "X" at 12433.46,3411.64 h60
  text "TOP" at 12559.46,3411.64 h60
  text "X" at 12943.46,3411.64 h60
  text "BOTTOM" at 13070.46,3411.64 h60
  text "SILKSCREEN COLOR:" at 11484.68,3244.64 h60
  text "X" at 12432.42,3244.64 h60
  text "WHITE" at 12559.46,3244.64 h60
  text "OTHER" at 13070.46,3244.64 h60
  text "X" at 12563.42,3085.44 h60
  text "GREEN" at 12690.46,3085.44 h60
  text "OTHER" at 13308.46,3085.44 h60
  text "SOLDER RESIST COLOR:" at 11484.68,3074.64 h60
  text "X" at 12563.42,2915.44 h60
  text "MATTE" at 12690.46,2915.44 h60
  text "SEMI-GLOSS" at 13308,2914.8 h60
  text "IMMERSION GOLD (ENIG)" at 12390.46,2726.92 h60
  text "ENEPIG" at 13728,2723.64 h60
  text "SURFACE FINISH:" at 11329.46,2722.64 h60
  text "X" at 12203.51,2722.64 h60
  text "IMM. TIN/SILVER OR EQUIV" at 11659,2565.64 h60
  text "OTHER" at 13090.46,2565.64 h60
  text "ARRAY/PANEL:" at 11329.46,2386.64 h60
  text "CUT AND TRIM PER M1 BOARD OUTLINE" at 12390.46,2382.35 h60
  text "N.C. ROUTE" at 12390.46,2230.64 h60
  text "X" at 13069.46,2230.64 h60
  text "V. SCORE" at 13256.46,2230.64 h60
  text "CERTIFICATION:" at 11329.46,2093.64 h60
  text "MATERIALS AND WORKMANSHIP FOR ALL PCBS" at 12054.46,2093.64 h60
  text "TO MEET OR EXCEED THE REQUIREMENTS OF:" at 12054.46,1995.64 h60
  text "X" at 11680.96,1859.13 h60
  text "ANSI IPC-A-600F CLASS ->" at 11819.96,1859.13 h60
  text "X" at 13459.02,1859.13 h60
  text "2" at 13577.96,1859.14 h60
  text "1" at 13262.96,1857.64 h60
  text "3" at 13931.96,1857.64 h60
  text "X" at 12495.02,1699.64 h60
  text "RoHS" at 12631.96,1699.64 h60
  text "OTHER" at 13276.36,1699.64 h60
  text "PER ORDER" at 13673.42,1699.64 h60
  text "ALL BOARDS MUST MEET OR EXCEED UL94-V0 REQUIREMENTS." at 11357,1534 h60
  text "PCB MUST BEAR THE UL94V-0 UL REGISTERED MATERIAL ID NUMBER" at 11357,1414 h60
  text "ADDITIONAL REQUIREMENTS:" at 11329.46,1240.64 h60
  text "MICROSECTION:" at 11404.23,1125.64 h60
  text "YES" at 12309.96,1125.64 h60
  text "REQUIRED" at 13171.46,969.49 h60
  text "BARE BOARD ELEC. TEST:" at 11404.23,966.64 h60
  text "NONE" at 12709.96,966.64 h60
  text "X" at 13044.46,966.64 h60
  text "PER ORDER" at 13763.46,966.64 h60
  text ".Layer_Name" at 577,-858.49 h60
M11 Gerber Information:
  lines w10: -292,-930.17 6308,-930.17 ; -292,-726.83 6310,-726.83 ; -292,-523.5 -292,-1133.5 3713,-1133.5 6310,-1133.5 6310,-523.5 -291.5,-523.5 -291.5,-1133.5 1284,-1133.5 ; 2173,-1133.5 2173,-523.5 ; 3440,-726.83 3440,-523.5 ; 4280,-726.83 4280,-523.5 ; 4902,-1140 4902,-937.17
  text "ALL ARTWORK VIEWED FROM TOP SIDE" at -228.5,-655.67 h60
  text "BOARD #:" at 2248,-655.67 h60
  text ".PRJ_Number" at 2793.5,-655.67 h60
  text "REV:" at 3638,-655.67 h60
  text ".PCB_Rev" at 3929.5,-655.67 h60
  text "SVN REV:" at 4476,-655.67 h60
  text ".VersionControl_RevNumber" at 4982,-655.67 h60
  text "LAYER NAME =" at -228.5,-858.49 h60
  text "TID #:" at 2248,-859 h60
  text ".TID" at 2793.5,-859 h60
  text "PLOT NAME =" at -228.5,-1064.34 h60
  text ".plot_File_Name" at 577,-1064.34 h60
  text "GENERATED    :" at 2250,-1064.34 h60
  text ".Print_Date" at 3119.5,-1064.34 h60
  text ".Print_Time" at 3848.5,-1064.34 h60
  text "TEXAS INSTRUMENTS" at 5113,-1064.34 h60
M12 Stackup:
  drawing of 191 lines, arcs and shapes, not listed
  text "Layer" at 9790.34,7830 h60
  text "Name" at 10200.26,7830 h60
  text "Material" at 11130,7830 h60
  text "Thickness" at 11989.77,7830 h60
  text "Constant" at 12639.6,7830 h60
  text "Board Layer Stack" at 13209.46,7830 h60
  text "1" at 9790.34,7710 h60
  text "Top Overlay" at 10200.26,7710 h60
  text "2" at 9790.34,7590 h60
  text "Top Solder" at 10200.26,7590 h60
  text "Solder Resist" at 11130,7590 h60
  text "0.40mil" at 11989.77,7590 h60
  text "3.5" at 12639.6,7590 h60
  text "3" at 9790.34,7470 h60
  text "Top Layer" at 10200.26,7470 h60
  text "Copper" at 11130,7470 h60
  text "1.40mil" at 11989.77,7470 h60
  text "4" at 9790.34,7350 h60
  text "Dielectric1" at 10200.26,7350 h60
  text "FR-4" at 11130,7350 h60
  text "59.20mil" at 11989.77,7350 h60
  text "4.8" at 12639.6,7350 h60
  text "5" at 9790.34,7230 h60
  text "Bottom Layer" at 10200.26,7230 h60
  text "Copper" at 11130,7230 h60
  text "1.40mil" at 11989.77,7230 h60
  text "6" at 9790.34,7110 h60
  text "Bottom Solder" at 10200.26,7110 h60
  text "Solder Resist" at 11130,7110 h60
  text "0.40mil" at 11989.77,7110 h60
  text "3.5" at 12639.6,7110 h60
  text "7" at 9790.34,6990 h60
  text "Bottom Overlay" at 10200.26,6990 h60
  text ".Layer_Name" at 577,-858.49 h60
M13 Component Bodies Top:
  text ".Layer_Name" at 577,-858.49 h60
M14 Component Bodies Bottom:
  text ".Layer_Name" at 577,-858.49 h60
M15 Courtyards Top:
  text ".Layer_Name" at 577,-858.49 h60
M16 Courtyards Bottom:
  text ".Layer_Name" at 577,-858.49 h60
Drill Drawing:
  circle w10: c5363.72,3017.64 r27.63
  lines w10: 5336.09,2396.04 5363.72,2368.42 5391.34,2396.04 5363.72,2423.67 5336.09,2396.04 ; 5336.09,2547.99 5391.34,2547.99 5363.72,2492.74 5336.09,2547.99 ; 5336.09,2617.06 5336.09,2630.87 5349.9,2644.68 5336.09,2658.5 5336.09,2672.31 5349.9,2672.31 5363.72,2658.5 5377.53,2672.31 5391.34,2672.31 5391.34,2658.5 5377.53,2644.68 5391.34,2630.87 5391.34,2617.06 5377.53,2617.06 5363.72,2630.87 5349.9,2617.06 5336.09,2617.06 ; 5336.09,2755.19 5349.9,2755.19 5349.9,2741.38 5377.53,2741.38 5377.53,2755.19 5391.34,2755.19 5391.34,2782.82 5377.53,2782.82 5377.53,2796.63 5349.9,2796.63 5349.9,2782.82 5336.09,2782.82 5336.09,2755.19 ; 5336.09,2879.51 5349.9,2879.51 5363.72,2865.7 5377.53,2879.51 5391.34,2879.51 5377.53,2893.32 5391.34,2907.14 5377.53,2907.14 5363.72,2920.95 5349.9,2907.14 5336.09,2907.14 5349.9,2893.32 5336.09,2879.51 ; 5336.09,3114.34 5363.72,3128.15 5391.34,3114.34 5377.53,3141.96 5391.34,3169.59 5363.72,3155.78 5336.09,3169.59 5349.9,3141.96 5336.09,3114.34 ; 5336.09,3238.66 5391.34,3238.66 5391.34,3293.91 5336.09,3293.91 5336.09,3238.66 ; 5347.14,3249.71 5380.29,3249.71 5380.29,3282.86 5347.14,3282.86 5347.14,3249.71
  lines w12: 5286,2331.12 8517.49,2331.12 ; 5286,3325.68 8517.49,3325.68 ; 5623.86,2206.8 5623.86,3450 ; 5955.86,2206.8 5955.86,3450 ; 6592.43,2206.8 6592.43,3450 ; 6851.57,2206.8 6851.57,3450 ; 7226.72,2206.8 7226.72,3450 ; 7951.05,2206.8 7951.05,3450 ; 5286,2206.8 8517.49,2206.8 8517.49,3450 5286,3450 5286,2206.8
  text "Symbol" at 5360.59,3362.98 h72
  text "Quantity" at 5661.16,3362.98 h72
  text "Finished Hole Size" at 5993.16,3362.98 h72
  text "Plated" at 6629.72,3362.98 h72
  text "Hole Type" at 6888.86,3362.98 h72
  text "Drill Layer Pair" at 7264.02,3362.98 h72
  text "Hole Tolerance" at 7988.35,3362.98 h72
  text "1" at 5661.16,3238.66 h60
  text "29.53mil (0.750mm)" at 5993.16,3238.66 h60
  text "NPTH" at 6629.72,3238.66 h60
  text "Round" at 6888.86,3238.66 h60
  text "Top Layer - Bottom Layer" at 7264.02,3238.66 h60
  text "40" at 5661.16,3114.34 h60
  text "11.81mil (0.300mm)" at 5993.16,3114.34 h60
  text "PTH" at 6629.72,3114.34 h60
  text "Round" at 6888.86,3114.34 h60
  text "Top Layer - Bottom Layer" at 7264.02,3114.34 h60
  text "2" at 5661.16,2990.02 h60
  text "16.00mil (0.406mm)" at 5993.16,2990.02 h60
  text "PTH" at 6629.72,2990.02 h60
  text "Round" at 6888.86,2990.02 h60
  text "Top Layer - Bottom Layer" at 7264.02,2990.02 h60
  text "1" at 5661.16,2865.7 h60
  text "28.00mil (0.711mm)" at 5993.16,2865.7 h60
  text "PTH" at 6629.72,2865.7 h60
  text "Round" at 6888.86,2865.7 h60
  text "Top Layer - Bottom Layer" at 7264.02,2865.7 h60
  text "2" at 5661.16,2741.38 h60
  text "29.53mil (0.750mm)" at 5993.16,2741.38 h60
  text "PTH" at 6629.72,2741.38 h60
  text "Round" at 6888.86,2741.38 h60
  text "Top Layer - Bottom Layer" at 7264.02,2741.38 h60
  text "4" at 5661.16,2617.06 h60
  text "39.37mil (1.000mm)" at 5993.16,2617.06 h60
  text "PTH" at 6629.72,2617.06 h60
  text "Round" at 6888.86,2617.06 h60
  text "Top Layer - Bottom Layer" at 7264.02,2617.06 h60
  text "20" at 5661.16,2492.74 h60
  text "45.28mil (1.150mm)" at 5993.16,2492.74 h60
  text "PTH" at 6629.72,2492.74 h60
  text "Round" at 6888.86,2492.74 h60
  text "Top Layer - Bottom Layer" at 7264.02,2492.74 h60
  text "1" at 5661.16,2368.42 h60
  text "63.00mil (1.600mm)" at 5993.16,2368.42 h60
  text "PTH" at 6629.72,2368.42 h60
  text "Round" at 6888.86,2368.42 h60
  text "Top Layer - Bottom Layer" at 7264.02,2368.42 h60
  text "71 Total" at 5661.16,2244.1 h60
  text ".Layer_Name" at 577,-858.49 h60
M17 Embedded Cavity:
  text ".Layer_Name" at 577,-858.49 h60
M18 Embedded Assembly:
  text ".Layer_Name" at 577,-858.49 h60
M19 Embedded Keepout:
  text ".Layer_Name" at 577,-858.49 h60

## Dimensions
0,-400 to 1000,-400 on M2 Board Dimensions
0,0 to 0,1700 on M2 Board Dimensions
0,0 to 2000,0 on M2 Board Dimensions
